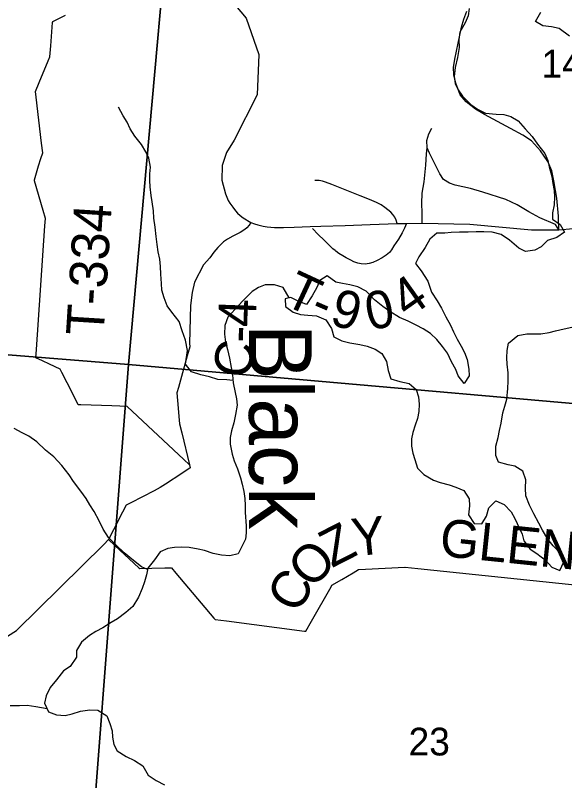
# Model space of a CAD drawing. Extents: x 0 to 42, y 0 to 22.
# Drawn here: x 3.807 to 4.221, y 14.736 to 15.313 of the extents above; entities that cross this region are included whole.
import ezdxf

# ---------------------------------------------------------------- set-up
doc = ezdxf.new("R2010")
doc.units = 0
for name, color, linetype in [('GM_X_County_Road', 7, 'Continuous'), ('GM_X_County_Road_Text', 7, 'Continuous'), ('GM_X_Major_Lake', 7, 'Continuous'), ('GM_X_Major_River', 7, 'Continuous'), ('GM_X_Major_River_Text', 7, 'Continuous'), ('GM_X_Minor_River', 7, 'Continuous'), ('GM_X_Section', 7, 'Continuous'), ('GM_X_Section_Text', 7, 'Continuous'), ('GM_X_State_Route', 7, 'Continuous'), ('GM_X_Township_Road', 7, 'Continuous'), ('GM_X_Township_Road_Text', 7, 'Continuous')]:
    doc.layers.add(name, color=color, linetype=linetype)

msp = doc.modelspace()

# ---------------------------------------------------------------- linework, layer by layer
at = {"layer": 'GM_X_County_Road'}
for points in [[(4.21669, 15.15127), (4.21651, 15.16164), (4.21519, 15.17528), (4.21304, 15.18816), (4.21132, 15.19589), (4.20846, 15.20276), (4.20288, 15.21078), (4.19615, 15.21837), (4.18956, 15.22266), (4.18026, 15.22781), (4.1605, 15.23827), (4.15378, 15.24227), (4.1469, 15.24786), (4.14232, 15.25315), (4.13889, 15.26203), (4.13746, 15.26832), (4.13732, 15.27376), (4.13832, 15.28006), (4.14318, 15.30411), (4.14505, 15.31027), (4.14719, 15.31614)], [(3.98435, 15.15675), (3.98307, 15.15482), (3.98124, 15.15278), (3.97993, 15.15154), (3.97626, 15.14935), (3.97067, 15.14645), (3.96682, 15.14432), (3.96373, 15.14221), (3.96143, 15.14007), (3.95952, 15.13797), (3.95647, 15.13432), (3.95332, 15.13019), (3.94869, 15.12479), (3.94184, 15.1117), (3.93997, 15.10401), (3.93892, 15.09423), (3.938, 15.0658), (3.93822, 15.06313), (3.93629, 15.05616), (3.92968, 15.03229), (3.92855, 15.0282), (3.92906, 15.02256), (3.93039, 15.00776), (3.93064, 15.00505), (3.9323, 14.99805), (3.93805, 14.97396), (3.9386, 14.97164), (3.9323, 14.96751), (3.91988, 14.95936), (3.91604, 14.95684), (3.91132, 14.9544), (3.8937, 14.94533), (3.89025, 14.94355), (3.88749, 14.9382), (3.88067, 14.925), (3.87687, 14.91766), (3.88173, 14.91318), (3.89996, 14.8964), (3.90049, 14.89591), (3.90966, 14.89606), (3.91957, 14.89621), (3.92438, 14.89629), (3.92767, 14.8924), (3.95651, 14.8584), (3.95737, 14.85737), (3.96587, 14.85627), (4.02483, 14.84858), (4.02581, 14.84845), (4.03021, 14.8562), (4.04488, 14.88205), (4.04553, 14.88318), (4.05295, 14.88753), (4.0615, 14.89253), (4.06562, 14.89495), (4.07074, 14.89523), (4.10042, 14.89683), (4.10089, 14.89685), (4.11027, 14.89586), (4.24823, 14.88135)], [(3.77408, 14.83911), (3.77653, 14.83915), (3.79601, 14.84185), (3.80746, 14.84902), (3.87332, 14.91401), (3.87687, 14.91766)]]:
    msp.add_lwpolyline(points, dxfattribs=at)
at = {"layer": 'GM_X_Major_Lake'}
for points in [[(4.149, 15.31831), (4.14819, 15.31282), (4.14606, 15.30734), (4.14203, 15.30037), (4.14122, 15.29488), (4.14154, 15.28881), (4.14034, 15.28124), (4.13838, 15.27386), (4.13775, 15.26704), (4.13845, 15.26173), (4.14087, 15.25696), (4.14403, 15.25201), (4.15022, 15.24588), (4.15529, 15.24242), (4.16131, 15.23933), (4.16943, 15.23849), (4.17529, 15.23825), (4.18038, 15.23687), (4.18602, 15.2334), (4.19125, 15.22748), (4.19649, 15.22174), (4.2006, 15.21601), (4.2062, 15.20875), (4.20842, 15.20362), (4.20951, 15.19887), (4.21134, 15.19164), (4.21223, 15.18614), (4.21313, 15.18101), (4.21346, 15.17627), (4.21322, 15.1702), (4.21203, 15.16415), (4.21198, 15.15922), (4.21762, 15.15538), (4.22096, 15.14947), (4.21507, 15.14554), (4.20805, 15.14333), (4.20328, 15.13845), (4.19853, 15.13584), (4.19153, 15.13496), (4.18663, 15.13747), (4.17951, 15.14342), (4.17312, 15.14784), (4.16633, 15.14942), (4.16009, 15.14986), (4.15442, 15.14973), (4.14818, 15.14959), (4.14176, 15.14947), (4.13551, 15.14915), (4.1306, 15.14882), (4.12474, 15.14887), (4.1194, 15.14418), (4.11594, 15.13796), (4.11115, 15.1308), (4.10864, 15.1259), (4.11294, 15.12036), (4.11797, 15.11254), (4.12073, 15.10436), (4.12501, 15.09768), (4.12818, 15.09216), (4.13133, 15.08568), (4.13505, 15.07939), (4.13727, 15.07425), (4.14006, 15.06872), (4.14303, 15.06358)], [(4.2248, 15.29749), (4.21691, 15.30325), (4.21106, 15.30444), (4.20464, 15.30507), (4.19919, 15.30835), (4.20323, 15.31551)], [(4.14303, 15.06358), (4.14545, 15.05882), (4.14748, 15.05349), (4.14892, 15.04627), (4.14906, 15.04115), (4.14523, 15.03531), (4.14074, 15.04104), (4.1389, 15.04599), (4.13574, 15.0517), (4.13259, 15.05818), (4.12904, 15.06333), (4.12474, 15.06868), (4.11987, 15.07309), (4.11423, 15.07655), (4.10915, 15.07926), (4.10313, 15.08235), (4.09654, 15.08526), (4.08921, 15.08969), (4.08395, 15.09334), (4.07757, 15.09852), (4.0714, 15.10502), (4.065, 15.10831), (4.05896, 15.10969), (4.05349, 15.11069), (4.04859, 15.11188), (4.04201, 15.11668), (4.0365, 15.11313), (4.03418, 15.10784), (4.03072, 15.10143), (4.02631, 15.09503), (4.01953, 15.09775), (4.01464, 15.10026), (4.01012, 15.09911), (4.01042, 15.09348), (4.01624, 15.08906), (4.02189, 15.08749), (4.02737, 15.08687), (4.03398, 15.08642), (4.04095, 15.08351), (4.04523, 15.07684), (4.04688, 15.07057), (4.05309, 15.06747), (4.05893, 15.06609), (4.06648, 15.06488), (4.07214, 15.0635), (4.07817, 15.06117), (4.08305, 15.0579), (4.08678, 15.05198), (4.08804, 15.04515), (4.09006, 15.03887), (4.09685, 15.03691), (4.10383, 15.03533), (4.10908, 15.03092), (4.11092, 15.02521), (4.11143, 15.0199), (4.11119, 15.01421), (4.11001, 15.00892), (4.10826, 15.004), (4.10651, 14.99852), (4.10552, 14.99361), (4.10566, 14.98811), (4.10655, 14.98279), (4.10802, 14.97804), (4.11004, 14.97157), (4.11491, 14.9666), (4.12224, 14.96254), (4.12714, 14.96079), (4.13393, 14.95902), (4.13902, 14.95726), (4.14504, 14.95455), (4.14914, 14.94845), (4.14928, 14.94314), (4.14865, 14.93632), (4.15275, 14.92983), (4.15861, 14.92959), (4.16225, 14.93524), (4.16383, 14.94167), (4.16917, 14.94674), (4.17557, 14.94421), (4.18062, 14.93867), (4.18341, 14.93352), (4.18916, 14.92171), (4.19025, 14.91658), (4.1951, 14.91047), (4.19999, 14.9072), (4.20675, 14.90202), (4.21142, 14.89685), (4.21745, 14.89433), (4.22054, 14.90094), (4.21832, 14.90684), (4.21233, 14.91296), (4.20841, 14.91793), (4.20431, 14.92479), (4.20172, 14.93012), (4.19781, 14.93717), (4.19447, 14.94365), (4.19189, 14.9505), (4.19156, 14.95638), (4.19181, 14.96282), (4.1896, 14.96929), (4.1834, 14.97295)], [(4.14303, 15.06358), (4.14545, 15.05882), (4.14748, 15.05349), (4.14892, 15.04627), (4.14906, 15.04115), (4.14523, 15.03531), (4.14074, 15.04104), (4.1389, 15.04599), (4.13574, 15.0517), (4.13259, 15.05818), (4.12904, 15.06333), (4.12474, 15.06868), (4.11987, 15.07309), (4.11423, 15.07655), (4.10915, 15.07926), (4.10313, 15.08235), (4.09654, 15.08526), (4.08921, 15.08969), (4.08395, 15.09334), (4.07757, 15.09852), (4.0714, 15.10502), (4.065, 15.10831), (4.05896, 15.10969), (4.05349, 15.11069), (4.04859, 15.11188), (4.04201, 15.11668), (4.0365, 15.11313), (4.03418, 15.10784), (4.03072, 15.10143), (4.02631, 15.09503), (4.01953, 15.09775), (4.01464, 15.10026), (4.01326, 15.09991)], [(4.01326, 15.09991), (4.01012, 15.09911), (4.01042, 15.09348), (4.01624, 15.08906), (4.02189, 15.08749), (4.02737, 15.08687), (4.03398, 15.08642), (4.04095, 15.08351), (4.04523, 15.07684), (4.04688, 15.07057), (4.05309, 15.06747), (4.05893, 15.06609), (4.06648, 15.06488), (4.07214, 15.0635), (4.07817, 15.06117), (4.08305, 15.0579), (4.08678, 15.05198), (4.08804, 15.04515), (4.09006, 15.03887), (4.09685, 15.03691), (4.10383, 15.03533), (4.10908, 15.03092), (4.11092, 15.02521), (4.11143, 15.0199), (4.11119, 15.01421), (4.11001, 15.00892), (4.10826, 15.004), (4.10651, 14.99852), (4.10552, 14.99361), (4.10566, 14.98811), (4.10655, 14.98279), (4.10802, 14.97804), (4.11004, 14.97157), (4.11491, 14.9666), (4.12224, 14.96254), (4.12714, 14.96079), (4.13393, 14.95902), (4.13902, 14.95726), (4.14504, 14.95455), (4.14914, 14.94845), (4.14928, 14.94314), (4.14865, 14.93632), (4.15275, 14.92983), (4.15861, 14.92959), (4.16225, 14.93524), (4.16383, 14.94167), (4.16917, 14.94674), (4.17557, 14.94421), (4.18062, 14.93867), (4.18341, 14.93352), (4.18916, 14.92171), (4.19025, 14.91658), (4.1951, 14.91047), (4.19999, 14.9072), (4.20675, 14.90202), (4.21142, 14.89685), (4.21745, 14.89433), (4.22054, 14.90094), (4.21832, 14.90684), (4.21233, 14.91296), (4.20841, 14.91793), (4.20431, 14.92479), (4.20172, 14.93012), (4.19781, 14.93717), (4.19447, 14.94365), (4.19189, 14.9505), (4.19156, 14.95638), (4.19181, 14.96282), (4.1896, 14.96929), (4.1834, 14.97295)], [(4.1834, 14.97295), (4.17849, 14.97395), (4.17114, 14.97591), (4.16911, 14.98105), (4.16917, 14.98807), (4.17094, 14.99468), (4.17193, 14.99998), (4.17312, 15.00547), (4.17451, 15.01323), (4.17588, 15.01833), (4.17744, 15.02344), (4.17827, 15.03158), (4.17852, 15.03708), (4.17838, 15.04333), (4.17769, 15.04997), (4.17755, 15.05472), (4.17779, 15.06021), (4.17878, 15.06589), (4.18583, 15.0717), (4.19265, 15.07277), (4.19775, 15.07272), (4.20305, 15.07286), (4.20929, 15.07394), (4.21422, 15.07522), (4.22066, 15.07648), (4.22653, 15.07775)]]:
    msp.add_lwpolyline(points, dxfattribs=at)
at = {"layer": 'GM_X_Major_River'}
msp.add_lwpolyline([(4.01326, 15.09991), (4.00871, 15.1078), (4.0021, 15.10973), (3.99511, 15.10976), (3.99019, 15.1077), (3.98527, 15.10488), (3.97843, 15.09771), (3.97255, 15.09148), (3.96704, 15.08544), (3.96474, 15.079), (3.96453, 15.07256), (3.96526, 15.06649), (3.96674, 15.06099), (3.96823, 15.05454), (3.96952, 15.04733), (3.97044, 15.04202), (3.97098, 15.03595), (3.97246, 15.02855), (3.97358, 15.02381), (3.97412, 15.01907), (3.97277, 15.01206), (3.97142, 15.00562), (3.96969, 14.99957), (3.96872, 14.99464), (3.9687, 14.98953), (3.97018, 14.98194), (3.97186, 14.977), (3.97429, 14.97092), (3.97653, 14.96428), (3.97783, 14.95935), (3.97894, 14.95385), (3.97986, 14.94853), (3.98003, 14.94342), (3.98001, 14.93811), (3.98072, 14.92787), (3.9807, 14.92275), (3.9803, 14.91783), (3.97467, 14.90683), (3.96861, 14.90532), (3.96229, 14.90597), (3.95587, 14.90714), (3.94946, 14.90944), (3.94455, 14.91041), (3.93794, 14.91177), (3.93171, 14.91179), (3.92679, 14.91163), (3.92169, 14.91089), (3.91582, 14.90846), (3.91163, 14.90241), (3.90669, 14.89599), (3.90573, 14.89106), (3.904, 14.88576), (3.90228, 14.88066), (3.89961, 14.87422), (3.89523, 14.86704), (3.89011, 14.86252), (3.88385, 14.85781), (3.87893, 14.85498), (3.87267, 14.85103), (3.86737, 14.84821), (3.86263, 14.8452), (3.85656, 14.8403), (3.85294, 14.83406), (3.85273, 14.82895), (3.84817, 14.82177), (3.84305, 14.81857), (3.83773, 14.81177), (3.83298, 14.8061), (3.82993, 14.79986), (3.82877, 14.79418), (3.83158, 14.78773), (3.83762, 14.78542), (3.84423, 14.78501), (3.84952, 14.78613), (3.85577, 14.78818), (3.86277, 14.7891), (3.86881, 14.78888), (3.87579, 14.78468), (3.87803, 14.77899), (3.8797, 14.77329), (3.88006, 14.76855), (3.88098, 14.76305), (3.88361, 14.7583), (3.8902, 14.75391), (3.89662, 14.75085), (3.90284, 14.74703), (3.90677, 14.73981), (3.91299, 14.7358), (3.91921, 14.73255)], dxfattribs=at)
at = {"layer": 'GM_X_Minor_River'}
for points in [[(3.97084, 15.03754), (3.96627, 15.03825), (3.95947, 15.03847), (3.95305, 15.04039), (3.94663, 15.04194), (3.93965, 15.04424), (3.93495, 15.04995), (3.9365, 15.06018), (3.93503, 15.06796), (3.9326, 15.07517), (3.93017, 15.08201), (3.92472, 15.08923), (3.92134, 15.09399), (3.91891, 15.09987), (3.91724, 15.10576), (3.91688, 15.11088), (3.91653, 15.11789), (3.91618, 15.12358), (3.91564, 15.12927), (3.91453, 15.13458), (3.91361, 15.14027), (3.91288, 15.14634), (3.91215, 15.15335), (3.91124, 15.16018), (3.91088, 15.16568), (3.90997, 15.17232), (3.90904, 15.17706), (3.9085, 15.1837), (3.90815, 15.18844), (3.90817, 15.19355), (3.90857, 15.19867), (3.90727, 15.20531), (3.90503, 15.21025), (3.90184, 15.21557), (3.89695, 15.22203), (3.89339, 15.22755), (3.89114, 15.23249), (3.88795, 15.23724), (3.88439, 15.24389)], [(3.9065, 14.89501), (3.90197, 14.89696), (3.89576, 14.90191), (3.88879, 14.90763), (3.88258, 14.91372), (3.87693, 14.91925), (3.87299, 14.92552), (3.86981, 14.93179), (3.86606, 14.93882), (3.86287, 14.94395), (3.86024, 14.9487), (3.85611, 14.95403), (3.85066, 14.96144), (3.84728, 14.96658), (3.84183, 14.97361), (3.83581, 14.98009), (3.82941, 14.98504), (3.82282, 14.99133), (3.81698, 14.99552), (3.81189, 14.9982), (3.80586, 15.00145)], [(3.83057, 14.79005), (3.82215, 14.79156), (3.81573, 14.79235), (3.80987, 14.79218), (3.80268, 14.79222)]]:
    msp.add_lwpolyline(points, dxfattribs=at)
at = {"layer": 'GM_X_Section'}
for points in [[(3.93759, 15.55646), (3.89198, 15.04961), (3.39711, 15.08946), (3.43811, 15.58616)], [(4.43443, 15.52355), (4.39069, 15.00589), (3.89198, 15.04961), (3.93759, 15.55646)], [(3.39711, 15.08946), (3.89198, 15.04961), (3.8526, 14.53574), (3.35135, 14.57775)], [(4.39069, 15.00589), (4.34454, 14.49165), (3.8526, 14.53574), (3.89198, 15.04961)]]:
    msp.add_lwpolyline(points, close=True, dxfattribs=at)
at = {"layer": 'GM_X_State_Route'}
for points in [[(3.97009, 15.32381), (3.98089, 15.31092), (3.99045, 15.28348), (3.9892, 15.25314), (3.97178, 15.219), (3.96597, 15.20963), (3.9626, 15.19969), (3.96241, 15.18881), (3.96522, 15.1785), (3.96617, 15.17586), (3.96732, 15.17352), (3.96857, 15.17132), (3.97065, 15.16826), (3.97275, 15.16566), (3.97426, 15.16392), (3.9763, 15.16222), (3.97848, 15.16039), (3.98435, 15.15675), (3.98711, 15.1559), (3.98962, 15.15498), (3.99375, 15.15405), (3.99664, 15.15361), (3.9995, 15.15334), (4.00225, 15.15317), (4.00888, 15.15307), (4.01707, 15.15332), (4.0292, 15.15373), (4.03726, 15.154), (4.05555, 15.15459), (4.07427, 15.15522), (4.09473, 15.15599), (4.10188, 15.15599), (4.11362, 15.15628), (4.14955, 15.15556), (4.19608, 15.15127), (4.21669, 15.15127)], [(4.21669, 15.15127), (4.22757, 15.15227), (4.24231, 15.15613), (4.25539, 15.16112)]]:
    msp.add_lwpolyline(points, dxfattribs=at)
at = {"layer": 'GM_X_Township_Road'}
for points in [[(3.88542, 15.01831), (3.87941, 15.0185), (3.85601, 15.01923), (3.85404, 15.01929), (3.84969, 15.02799), (3.84185, 15.0437), (3.84058, 15.04624), (3.83254, 15.04997), (3.82723, 15.05244), (3.82219, 15.05478), (3.82261, 15.06091), (3.82904, 15.15434), (3.82939, 15.15974), (3.82767, 15.16579), (3.82124, 15.1883), (3.82105, 15.18898), (3.82426, 15.1995), (3.82597, 15.20509), (3.82731, 15.20947), (3.82646, 15.21655), (3.82231, 15.25142), (3.82181, 15.2556), (3.82471, 15.26251), (3.83151, 15.2787), (3.83281, 15.28179), (3.83345, 15.29012), (3.83482, 15.30763), (3.83489, 15.30855), (3.84462, 15.31317)], [(4.21669, 15.15127), (4.21414, 15.1552), (4.20225, 15.16035), (4.19417, 15.16476), (4.18534, 15.17003), (4.17677, 15.17419), (4.15936, 15.17959), (4.15017, 15.18253), (4.13853, 15.18498), (4.13412, 15.18645), (4.12971, 15.18914), (4.12702, 15.19343), (4.11917, 15.20924), (4.11734, 15.21304), (4.11721, 15.2188), (4.11856, 15.22382), (4.12077, 15.22799)], [(4.11362, 15.15628), (4.11364, 15.16414), (4.1133, 15.17122), (4.11372, 15.1789), (4.11509, 15.18744), (4.11637, 15.19998), (4.11688, 15.2086), (4.11734, 15.21304)], [(4.09473, 15.15599), (4.09394, 15.15851), (4.09292, 15.16088), (4.09154, 15.16285), (4.08986, 15.16453), (4.08769, 15.16647), (4.08539, 15.16824), (4.08263, 15.17005), (4.07904, 15.17183), (4.07378, 15.17419), (4.06678, 15.17702), (4.05672, 15.18084), (4.04554, 15.18544), (4.04057, 15.18728), (4.0383, 15.188), (4.03587, 15.18853), (4.03267, 15.18857)], [(4.04796, 15.13561), (4.04631, 15.13696), (4.04302, 15.14012), (4.03969, 15.14353), (4.03526, 15.14785), (4.03076, 15.15236)], [(4.10188, 15.15599), (4.10028, 15.15245), (4.09859, 15.14896), (4.09584, 15.14423), (4.09234, 15.1393), (4.09058, 15.13609), (4.08906, 15.13416), (4.08634, 15.13211), (4.08351, 15.13016), (4.07973, 15.12808), (4.07632, 15.12672), (4.07373, 15.1259), (4.07068, 15.12549), (4.06768, 15.12565), (4.06509, 15.12611), (4.06214, 15.12722), (4.05967, 15.12833), (4.05618, 15.13013), (4.05363, 15.1317), (4.05075, 15.13338), (4.04837, 15.13527), (4.04796, 15.13561)], [(3.93805, 14.97396), (3.93377, 14.97796), (3.89104, 15.01795), (3.88542, 15.01831)]]:
    msp.add_lwpolyline(points, dxfattribs=at)

# ---------------------------------------------------------------- texts
at = {"layer": 'GM_X_County_Road_Text'}
for s, height, rotation, p in [('4', 0.02841, 87.9648, (3.98795, 15.07755)), ('-', 0.02841, 88.96279, (3.98774, 15.06602)), ('C', 0.02841, 79.39736, (3.98293, 15.03794)), ('Y', 0.02841, 5.67725, (4.0617, 14.90489)), ('GLENN', 0.028409, 354.11426, (4.12595, 14.90544)), ('Z', 0.02841, 27.03654, (4.04544, 14.89601)), ('O', 0.02841, 46.21843, (4.03015, 14.87946)), ('C', 0.02841, 60.23914, (4.01967, 14.86067))]:
    msp.add_text(s, height=height, rotation=rotation, dxfattribs=at).set_placement(p)
at = {"layer": 'GM_X_Major_River_Text'}
msp.add_text('Black', height=0.047353, rotation=270.00032, dxfattribs=at).set_placement((3.98298, 15.08049))
at = {"layer": 'GM_X_Section_Text'}
for s, p in [('14', (4.20356, 15.26617)), ('23', (4.10335, 14.75477))]:
    msp.add_text(s, height=0.020928, rotation=0.00001, dxfattribs=at).set_placement(p)
at = {"layer": 'GM_X_Township_Road_Text'}
for s, height, rotation, p in [('T-334', 0.028409, 86.39079, (3.87319, 15.07083)), ('T', 0.02841, 335.08538, (4.00769, 15.09548)), ('4', 0.02841, 35.37855, (4.10276, 15.08376)), ('9', 0.02841, 345.45245, (4.04294, 15.08001)), ('0', 0.02841, 11.25766, (4.07371, 15.07522)), ('-', 0.02841, 336.66114, (4.02774, 15.08618))]:
    msp.add_text(s, height=height, rotation=rotation, dxfattribs=at).set_placement(p)

doc.saveas('drawing.dxf')
